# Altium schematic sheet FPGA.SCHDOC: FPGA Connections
size A2; Organization: Altium Limited.; Address1: Level 3, 12a Rodborough Rd; Address2: Frenchs Forest 2086; Address3: NSW; Address4: AUSTRALIA; SheetNumber: 6; SheetTotal: 19; PageSetup: Record=PageOptions|CenterHorizontal=True|CenterVertical=True|PrintScale=0.71|XCorrection=1.00|YCorrection=1.00|PrintKind=0|BorderSize=5000000|LeftOffset=0|BottomOffset=0|Orientation=2|PaperLength=1000|PaperWidth=1000|Scale=100|PaperSource=7|PrintQuality=600|MediaType=1|DitherType=10|PaperKind=A3 (297 x 420mm)|PrintScaleMode=1
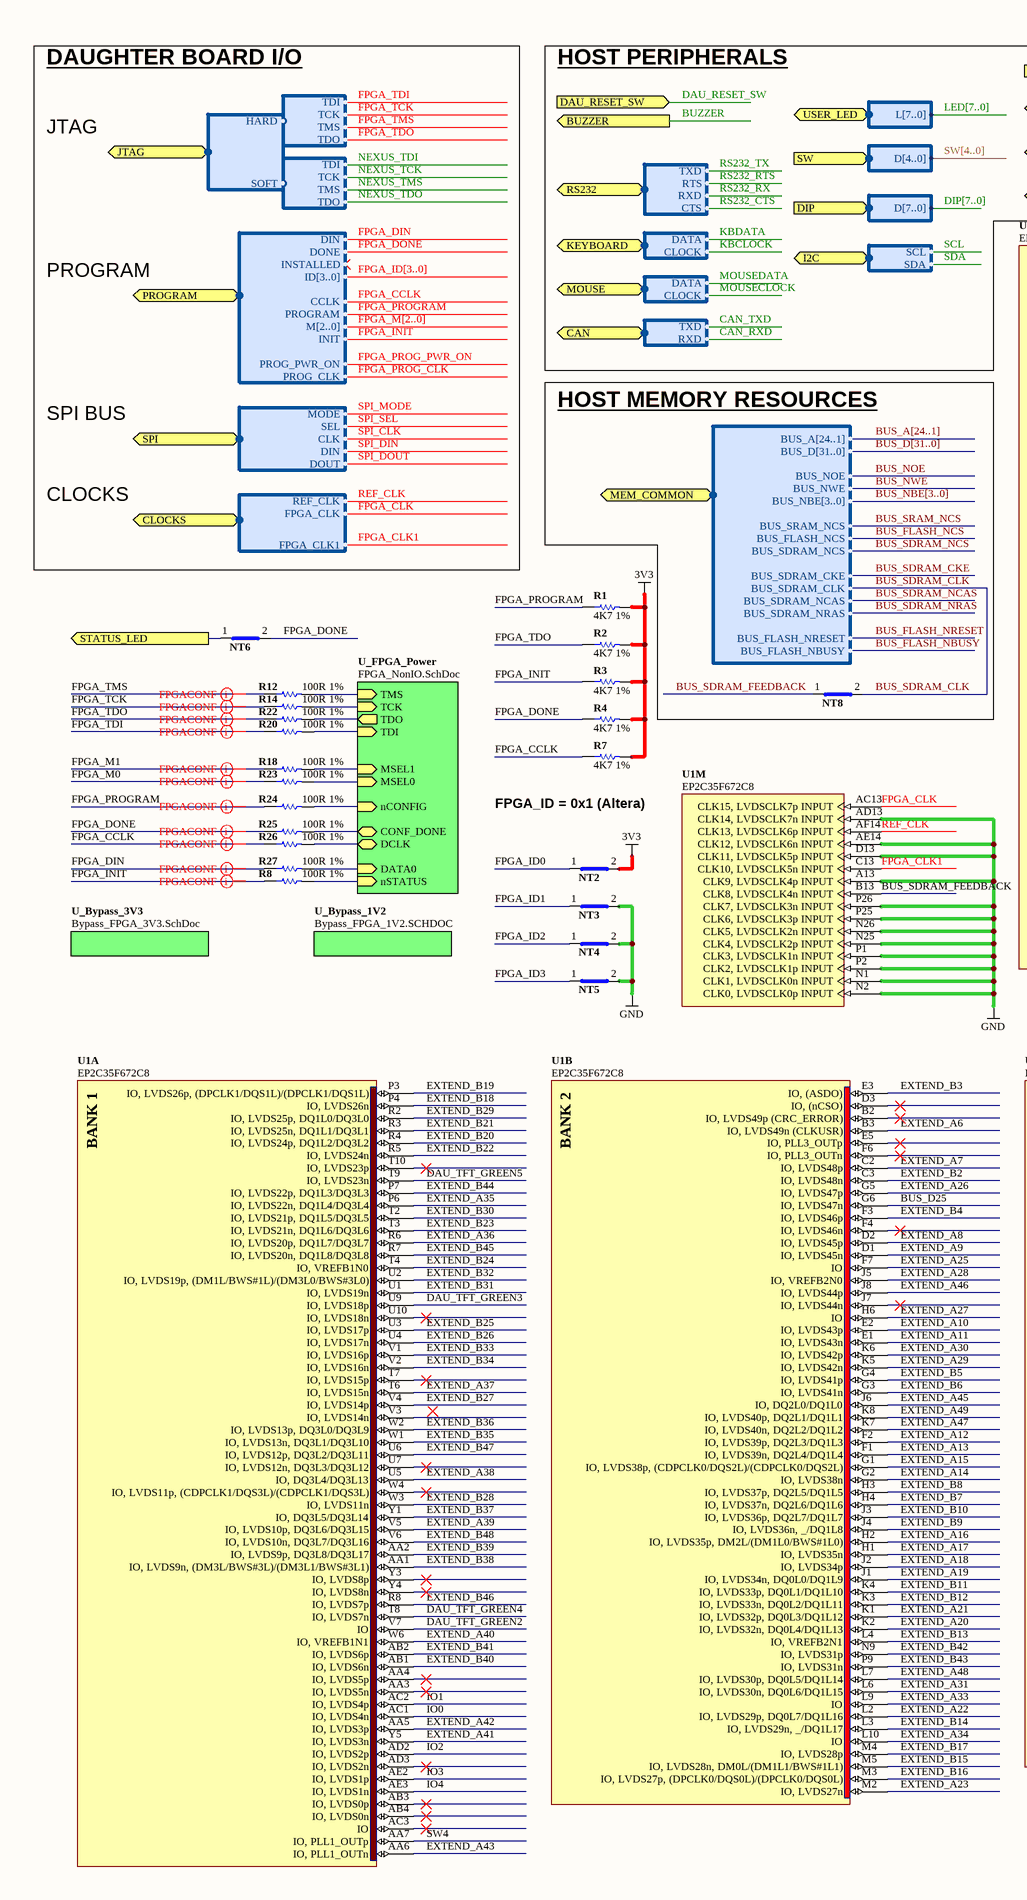
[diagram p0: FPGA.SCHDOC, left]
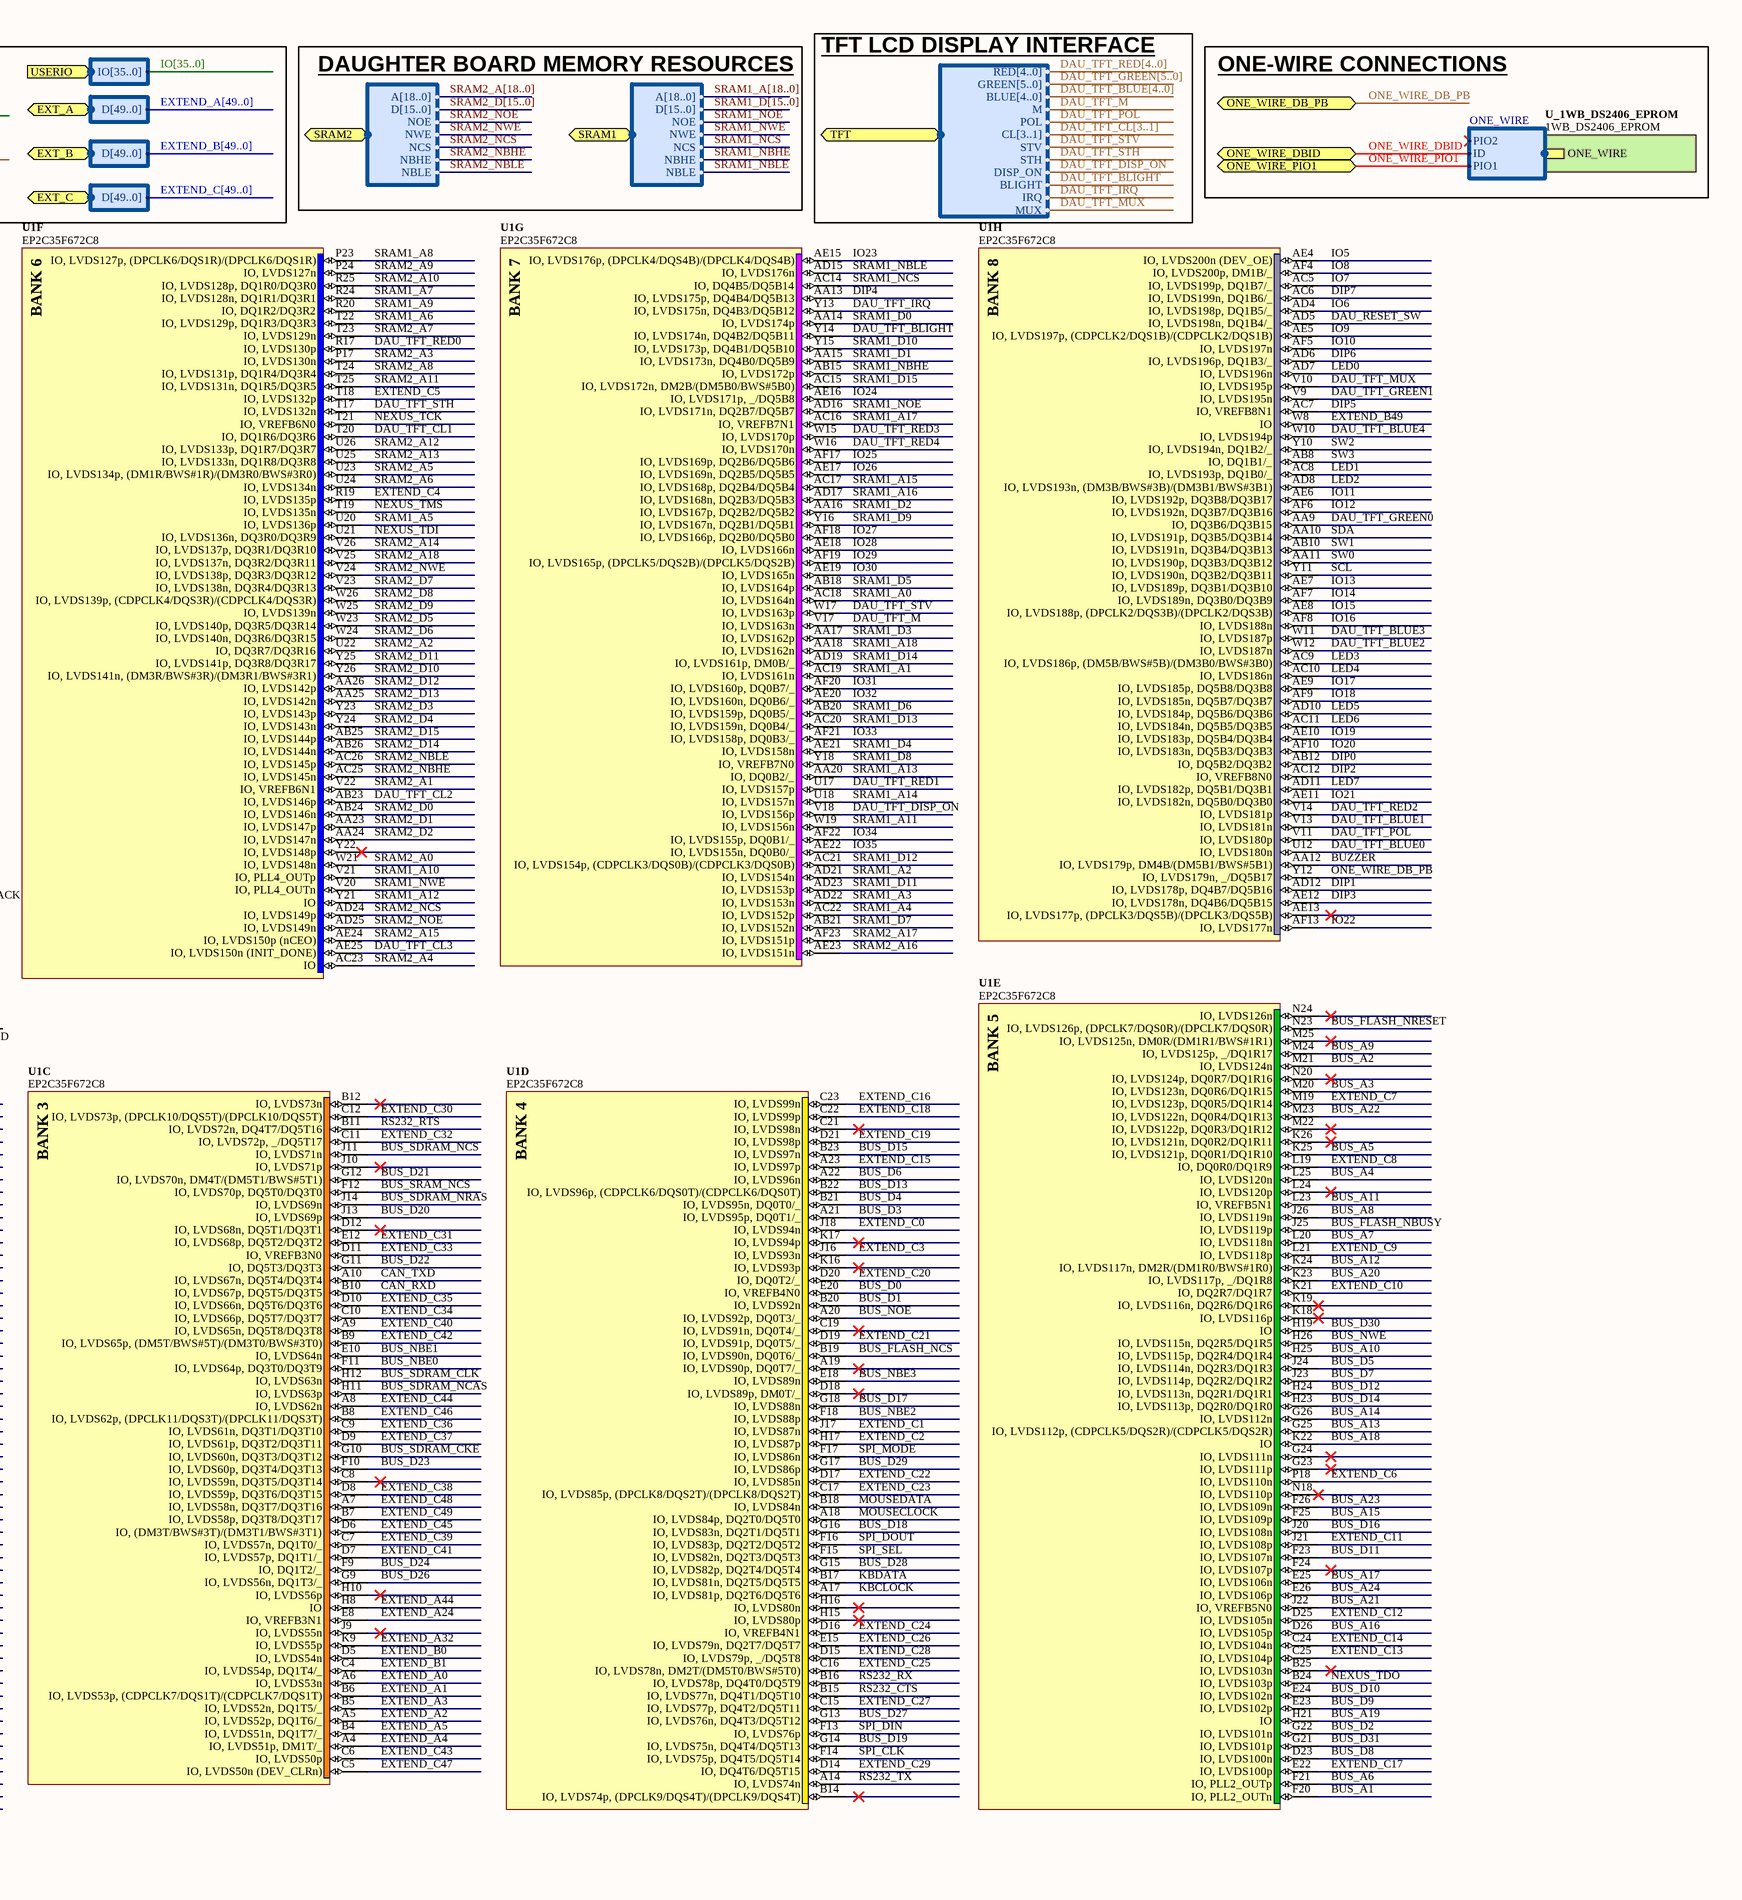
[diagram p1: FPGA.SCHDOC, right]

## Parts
NT2  Net Tie SMT2  [NETTIE-SMT2-8X8]  (value not drawn)  (net tie, no BOM)
NT3  Net Tie SMT2  [NETTIE-SMT2-8X8]  (value not drawn)  (net tie, no BOM)
NT4  Net Tie SMT2  [NETTIE-SMT2-8X8]  (value not drawn)  (net tie, no BOM)
NT5  Net Tie SMT2  [NETTIE-SMT2-8X8]  (value not drawn)  (net tie, no BOM)
NT6  Net Tie SMT2  [NETTIE-SMT2-8X8]  (value not drawn)  (net tie, no BOM)
NT8  Net Tie SMT2  [NETTIE-SMT2-8X8]  (value not drawn)  (net tie, no BOM)
R1  4K7 1%  [RESC1005-STAR]
R2  4K7 1%  [RESC1005-STAR]
R3  4K7 1%  [RESC1005-STAR]
R4  4K7 1%  [RESC1005-STAR]
R7  4K7 1%  [RESC1005-STAR]
R8  100R 1%  [RESC1005-STAR]
R12  100R 1%  [RESC1005-STAR]
R14  100R 1%  [RESC1005-STAR]
R18  100R 1%  [RESC1005-STAR]
R20  100R 1%  [RESC1005-STAR]
R22  100R 1%  [RESC1005-STAR]
R23  100R 1%  [RESC1005-STAR]
R24  100R 1%  [RESC1005-STAR]
R25  100R 1%  [RESC1005-STAR]
R26  100R 1%  [RESC1005-STAR]
R27  100R 1%  [RESC1005-STAR]
U1  EP2C35F672C8  [BGA100P26X26-672]  (parts A,B,C,D,E,F,G,H,M of 14)

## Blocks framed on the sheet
HOST MEMORY RESOURCES: NT8

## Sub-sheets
U_1WB_DS2406_EPROM = 1WB_DS2406_EPROM: ONE_WIRE (harness ONE_WIRE)
U_Bypass_1V2 = Bypass_FPGA_1V2.SCHDOC: no entries
U_Bypass_3V3 = Bypass_FPGA_3V3.SchDoc: no entries
U_FPGA_Power = FPGA_NonIO.SchDoc: TMS (in), CONF_DONE (bidir), MSEL1 (in), DCLK (bidir), MSEL0 (in), DATA0 (in), TCK (in), nSTATUS (in), TDI (in), nCONFIG (in), TDO (out)

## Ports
BUZZER (out), CAN (harness CAN_INT), CLOCKS (harness DAU_CLK), DAU_RESET_SW (in), DIP (harness SW8), EXT_A (harness PBIO), EXT_B (harness PBIO), EXT_C (harness PBIO), I2C (harness I2C), JTAG (harness HARDSOFT_JTAG), KEYBOARD (harness PS2), MEM_COMMON (harness HOSTMEMORY), MOUSE (harness PS2), ONE_WIRE_DB_PB (bidir), ONE_WIRE_DBID (bidir), ONE_WIRE_PIO1 (bidir), PROGRAM (harness DAU_CTRL), RS232 (harness RS232_INT), SPI (harness DAU_SPI), SRAM1 (harness SRAM-256Kx16), SRAM2 (harness SRAM-256Kx16), STATUS_LED (out), SW (harness SW5), TFT (harness DAU_TFT), USER_LED (harness LED8), USERIO (harness IO36)

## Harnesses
ONE_WIRE: ID, PIO1, PIO2
DAU_CLK: REF_CLK, FPGA_CLK, FPGA_CLK1
DAU_SPI: MODE, SEL, CLK, DIN, DOUT
DAU_CTRL: DIN, DONE, INSTALLED, ID[3..0], CCLK, PROGRAM, M[2..0], INIT, PROG_PWR_ON, PROG_CLK
JTAG: TMS, TDO, TDI, TCK
HARDSOFT_JTAG: HARD, SOFT
DAU_TFT: RED[4..0], GREEN[5..0], BLUE[4..0], M, POL, CL[3..1], STV, STH, DISP_ON, BLIGHT, IRQ, MUX
SRAM-256Kx16: A[18..0], D[15..0], NCS, NWE, NOE, NBHE, NBLE
HOSTMEMORY: BUS_A[24..1], BUS_D[31..0], BUS_NOE, BUS_NWE, BUS_NBE[3..0], BUS_SRAM_NCS, BUS_FLASH_NCS, BUS_SDRAM_NCS, BUS_SDRAM_CKE, BUS_SDRAM_CLK, BUS_SDRAM_NCAS, BUS_SDRAM_NRAS, BUS_FLASH_NRESET, BUS_FLASH_NBUSY
LED8: L[7..0]
SW5: D[4..0]
PS2: DATA, CLOCK
RS232_INT: RXD, TXD, RTS, CTS
PBIO: D[49..0]
IO36: IO[35..0]
SW8: D[7..0]
CAN_INT: TXD, RXD
I2C: SCL, SDA

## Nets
3V3: NT2.2(Net2) R1.2 R2.2 R3.2 R4.2 R7.2
GND: NT3.2(Net2) NT4.2(Net2) NT5.2(Net2) U1.A13(CLK9,_LVDSCLK4p_INPUT) U1.AD13(CLK14,_LVDSCLK7n_INPUT) U1.AE14(CLK12,_LVDSCLK6n_INPUT) U1.D13(CLK11,_LVDSCLK5p_INPUT) U1.N1(CLK1,_LVDSCLK0n_INPUT) U1.N2(CLK0,_LVDSCLK0p_INPUT) U1.N25(CLK4,_LVDSCLK2p_INPUT) U1.N26(CLK5,_LVDSCLK2n_INPUT) U1.P1(CLK3,_LVDSCLK1n_INPUT) U1.P2(CLK2,_LVDSCLK1p_INPUT) U1.P25(CLK6,_LVDSCLK3p_INPUT) U1.P26(CLK7,_LVDSCLK3n_INPUT)
BUS_A1: U1.F20(IO,_PLL2_OUTn)
BUS_A2: U1.M21(IO,_LVDS124n)
BUS_A3: U1.M20(IO,_LVDS123n,_DQ0R6/DQ1R15)
BUS_A4: U1.L25(IO,_LVDS120n)
BUS_A5: U1.K25(IO,_LVDS121p,_DQ0R1/DQ1R10)
BUS_A6: U1.F21(IO,_PLL2_OUTp)
BUS_A7: U1.L20(IO,_LVDS118n)
BUS_A8: U1.J26(IO,_LVDS119n)
BUS_A9: U1.M24(IO,_LVDS125p,__/DQ1R17)
BUS_A10: U1.H25(IO,_LVDS115p,_DQ2R4/DQ1R4)
BUS_A11: U1.L23(IO,_VREFB5N1)
BUS_A12: U1.K24(IO,_LVDS117n,_DM2R/(DM1R0/BWS#1R0))
BUS_A13: U1.G25(IO,_LVDS112p,_(CDPCLK5/DQS2R)/(CDPCLK5/DQS2R))
BUS_A14: U1.G26(IO,_LVDS112n)
BUS_A15: U1.F25(IO,_LVDS109p)
BUS_A16: U1.D26(IO,_LVDS105p)
BUS_A17: U1.E25(IO,_LVDS106n)
BUS_A18: U1.K22(IO)
BUS_A19: U1.H21(IO)
BUS_A20: U1.K23(IO,_LVDS117p,__/DQ1R8)
BUS_A21: U1.J22(IO,_VREFB5N0)
BUS_A22: U1.M23(IO,_LVDS122n,_DQ0R4/DQ1R13)
BUS_A23: U1.F26(IO,_LVDS109n)
BUS_A24: U1.E26(IO,_LVDS106p)
BUS_D0: U1.E20(IO,_VREFB4N0)
BUS_D1: U1.B20(IO,_LVDS92n)
BUS_D2: U1.G22(IO,_LVDS101n)
BUS_D3: U1.A21(IO,_LVDS95p,_DQ0T1/_)
BUS_D4: U1.B21(IO,_LVDS95n,_DQ0T0/_)
BUS_D5: U1.J24(IO,_LVDS114n,_DQ2R3/DQ1R3)
BUS_D6: U1.A22(IO,_LVDS96n)
BUS_D7: U1.J23(IO,_LVDS114p,_DQ2R2/DQ1R2)
BUS_D8: U1.D23(IO,_LVDS100n)
BUS_D9: U1.E23(IO,_LVDS102p)
BUS_D10: U1.E24(IO,_LVDS102n)
BUS_D11: U1.F23(IO,_LVDS107n)
BUS_D12: U1.H24(IO,_LVDS113n,_DQ2R1/DQ1R1)
BUS_D13: U1.B22(IO,_LVDS96p,_(CDPCLK6/DQS0T)/(CDPCLK6/DQS0T))
BUS_D14: U1.H23(IO,_LVDS113p,_DQ2R0/DQ1R0)
BUS_D15: U1.B23(IO,_LVDS97n)
BUS_D16: U1.J20(IO,_LVDS108n)
BUS_D17: U1.G18(IO,_LVDS88n)
BUS_D18: U1.G16(IO,_LVDS83n,_DQ2T1/DQ5T1)
BUS_D19: U1.G14(IO,_LVDS75n,_DQ4T4/DQ5T13)
BUS_D20: U1.J13(IO,_LVDS69p)
BUS_D21: U1.G12(IO,_LVDS70n,_DM4T/(DM5T1/BWS#5T1))
BUS_D22: U1.G11(IO,_DQ5T3/DQ3T3)
BUS_D23: U1.F10(IO,_LVDS60p,_DQ3T4/DQ3T13)
BUS_D24: U1.F9(IO,_DQ1T2/_)
BUS_D25: U1.G6(IO,_LVDS47n)
BUS_D26: U1.G9(IO,_LVDS56n,_DQ1T3/_)
BUS_D27: U1.G13(IO,_LVDS76n,_DQ4T3/DQ5T12)
BUS_D28: U1.G15(IO,_LVDS82p,_DQ2T4/DQ5T4)
BUS_D29: U1.G17(IO,_LVDS86p)
BUS_D30: U1.H19(IO)
BUS_D31: U1.G21(IO,_LVDS101p)
BUS_FLASH_NBUSY: U1.J25(IO,_LVDS119p) ; port MEM_COMMON.BUS_FLASH_NBUSY
BUS_FLASH_NCS: U1.B19(IO,_LVDS90n,_DQ0T6/_) ; port MEM_COMMON.BUS_FLASH_NCS
BUS_FLASH_NRESET: U1.N23(IO,_LVDS126p,_(DPCLK7/DQS0R)/(DPCLK7/DQS0R)) ; port MEM_COMMON.BUS_FLASH_NRESET
BUS_NBE0: U1.F11(IO,_LVDS64p,_DQ3T0/DQ3T9)
BUS_NBE1: U1.E10(IO,_LVDS64n)
BUS_NBE2: U1.F18(IO,_LVDS88p)
BUS_NBE3: U1.E18(IO,_LVDS89n)
BUS_NOE: U1.A20(IO,_LVDS92p,_DQ0T3/_) ; port MEM_COMMON.BUS_NOE
BUS_NWE: U1.H26(IO,_LVDS115n,_DQ2R5/DQ1R5) ; port MEM_COMMON.BUS_NWE
BUS_SDRAM_CKE: U1.G10(IO,_LVDS60n,_DQ3T3/DQ3T12) ; port MEM_COMMON.BUS_SDRAM_CKE
BUS_SDRAM_CLK: NT8.2(Net2) U1.H12(IO,_LVDS63n) ; port MEM_COMMON.BUS_SDRAM_CLK
BUS_SDRAM_FEEDBACK: NT8.1(Net1) U1.B13(CLK8,_LVDSCLK4n_INPUT)
BUS_SDRAM_NCAS: U1.H11(IO,_LVDS63p) ; port MEM_COMMON.BUS_SDRAM_NCAS
BUS_SDRAM_NCS: U1.J11(IO,_LVDS71n) ; port MEM_COMMON.BUS_SDRAM_NCS
BUS_SDRAM_NRAS: U1.J14(IO,_LVDS69n) ; port MEM_COMMON.BUS_SDRAM_NRAS
BUS_SRAM_NCS: U1.F12(IO,_LVDS70p,_DQ5T0/DQ3T0) ; port MEM_COMMON.BUS_SRAM_NCS
BUZZER: U1.AA12(IO,_LVDS179p,_DM4B/(DM5B1/BWS#5B1)) ; port BUZZER
CAN_RXD: U1.B10(IO,_LVDS67p,_DQ5T5/DQ3T5) ; port CAN.RXD
CAN_TXD: U1.A10(IO,_LVDS67n,_DQ5T4/DQ3T4) ; port CAN.TXD
DAU_RESET_SW: U1.AD5(IO,_LVDS198n,_DQ1B4/_) ; port DAU_RESET_SW
DAU_TFT_BLIGHT: U1.Y14(IO,_LVDS174n,_DQ4B2/DQ5B11) ; port TFT.BLIGHT
DAU_TFT_BLUE0: U1.U12(IO,_LVDS180n)
DAU_TFT_BLUE1: U1.V13(IO,_LVDS181n)
DAU_TFT_BLUE2: U1.W12(IO,_LVDS187n)
DAU_TFT_BLUE3: U1.W11(IO,_LVDS187p)
DAU_TFT_BLUE4: U1.W10(IO,_LVDS194p)
DAU_TFT_CL1: U1.T20(IO,_DQ1R6/DQ3R6)
DAU_TFT_CL2: U1.AB23(IO,_LVDS146p)
DAU_TFT_CL3: U1.AE25(IO,_LVDS150n_(INIT_DONE))
DAU_TFT_DISP_ON: U1.V18(IO,_LVDS156p) ; port TFT.DISP_ON
DAU_TFT_GREEN0: U1.AA9(IO,_DQ3B6/DQ3B15)
DAU_TFT_GREEN1: U1.V9(IO,_LVDS195n)
DAU_TFT_GREEN2: U1.V7(IO)
DAU_TFT_GREEN3: U1.U9(IO,_LVDS18p)
DAU_TFT_GREEN4: U1.T8(IO,_LVDS7n)
DAU_TFT_GREEN5: U1.T9(IO,_LVDS23n)
DAU_TFT_IRQ: U1.Y13(IO,_LVDS175n,_DQ4B3/DQ5B12) ; port TFT.IRQ
DAU_TFT_M: U1.V17(IO,_LVDS163n) ; port TFT.M
DAU_TFT_MUX: U1.V10(IO,_LVDS195p) ; port TFT.MUX
DAU_TFT_POL: U1.V11(IO,_LVDS180p) ; port TFT.POL
DAU_TFT_RED0: U1.R17(IO,_LVDS130p)
DAU_TFT_RED1: U1.U17(IO,_LVDS157p)
DAU_TFT_RED2: U1.V14(IO,_LVDS181p)
DAU_TFT_RED3: U1.W15(IO,_LVDS170p)
DAU_TFT_RED4: U1.W16(IO,_LVDS170n)
DAU_TFT_STH: U1.T17(IO,_LVDS132n) ; port TFT.STH
DAU_TFT_STV: U1.W17(IO,_LVDS163p) ; port TFT.STV
DIP0: U1.AB12(IO,_DQ5B2/DQ3B2)
DIP1: U1.AD12(IO,_LVDS178p,_DQ4B7/DQ5B16)
DIP2: U1.AC12(IO,_VREFB8N0)
DIP3: U1.AE12(IO,_LVDS178n,_DQ4B6/DQ5B15)
DIP4: U1.AA13(IO,_LVDS175p,_DQ4B4/DQ5B13)
DIP5: U1.AC7(IO,_VREFB8N1)
DIP6: U1.AD6(IO,_LVDS196p,_DQ1B3/_)
DIP7: U1.AC6(IO,_LVDS199n,_DQ1B6/_)
EXTEND_A0: U1.A6(IO,_LVDS53n)
EXTEND_A1: U1.B6(IO,_LVDS53p,_(CDPCLK7/DQS1T)/(CDPCLK7/DQS1T))
EXTEND_A2: U1.A5(IO,_LVDS52p,_DQ1T6/_)
EXTEND_A3: U1.B5(IO,_LVDS52n,_DQ1T5/_)
EXTEND_A4: U1.A4(IO,_LVDS51p,_DM1T/_)
EXTEND_A5: U1.B4(IO,_LVDS51n,_DQ1T7/_)
EXTEND_A6: U1.B3(IO,_LVDS49n_(CLKUSR))
EXTEND_A7: U1.C2(IO,_LVDS48p)
EXTEND_A8: U1.D2(IO,_LVDS45p)
EXTEND_A9: U1.D1(IO,_LVDS45n)
EXTEND_A10: U1.E2(IO,_LVDS43p)
EXTEND_A11: U1.E1(IO,_LVDS43n)
EXTEND_A12: U1.F2(IO,_LVDS39p,_DQ2L3/DQ1L3)
EXTEND_A13: U1.F1(IO,_LVDS39n,_DQ2L4/DQ1L4)
EXTEND_A14: U1.G2(IO,_LVDS38n)
EXTEND_A15: U1.G1(IO,_LVDS38p,_(CDPCLK0/DQS2L)/(CDPCLK0/DQS2L))
EXTEND_A16: U1.H2(IO,_LVDS35p,_DM2L/(DM1L0/BWS#1L0))
EXTEND_A17: U1.H1(IO,_LVDS35n)
EXTEND_A18: U1.J2(IO,_LVDS34p)
EXTEND_A19: U1.J1(IO,_LVDS34n,_DQ0L0/DQ1L9)
EXTEND_A20: U1.K2(IO,_LVDS32n,_DQ0L4/DQ1L13)
EXTEND_A21: U1.K1(IO,_LVDS32p,_DQ0L3/DQ1L12)
EXTEND_A22: U1.L2(IO,_LVDS29p,_DQ0L7/DQ1L16)
EXTEND_A23: U1.M2(IO,_LVDS27n)
EXTEND_A24: U1.E8(IO,_VREFB3N1)
EXTEND_A25: U1.F7(IO)
EXTEND_A26: U1.G5(IO,_LVDS47p)
EXTEND_A27: U1.H6(IO)
EXTEND_A28: U1.J5(IO,_VREFB2N0)
EXTEND_A29: U1.K5(IO,_LVDS42n)
EXTEND_A30: U1.K6(IO,_LVDS42p)
EXTEND_A31: U1.L6(IO,_LVDS30n,_DQ0L6/DQ1L15)
EXTEND_A32: U1.K9(IO,_LVDS55p)
EXTEND_A33: U1.L9(IO)
EXTEND_A34: U1.L10(IO)
EXTEND_A35: U1.P6(IO,_LVDS22n,_DQ1L4/DQ3L4)
EXTEND_A36: U1.R6(IO,_LVDS20p,_DQ1L7/DQ3L7)
EXTEND_A37: U1.T6(IO,_LVDS15n)
EXTEND_A38: U1.U5(IO,_DQ3L4/DQ3L13)
EXTEND_A39: U1.V5(IO,_LVDS10p,_DQ3L6/DQ3L15)
EXTEND_A40: U1.W6(IO,_VREFB1N1)
EXTEND_A41: U1.Y5(IO,_LVDS3n)
EXTEND_A42: U1.AA5(IO,_LVDS3p)
EXTEND_A43: U1.AA6(IO,_PLL1_OUTn)
EXTEND_A44: U1.H8(IO)
EXTEND_A45: U1.J6(IO,_DQ2L0/DQ1L0)
EXTEND_A46: U1.J8(IO,_LVDS44p)
EXTEND_A47: U1.K7(IO,_LVDS40n,_DQ2L2/DQ1L2)
EXTEND_A48: U1.L7(IO,_LVDS30p,_DQ0L5/DQ1L14)
EXTEND_A49: U1.K8(IO,_LVDS40p,_DQ2L1/DQ1L1)
EXTEND_B0: U1.D5(IO,_LVDS54n)
EXTEND_B1: U1.C4(IO,_LVDS54p,_DQ1T4/_)
EXTEND_B2: U1.C3(IO,_LVDS48n)
EXTEND_B3: U1.E3(IO,_(ASDO))
EXTEND_B4: U1.F3(IO,_LVDS46p)
EXTEND_B5: U1.G4(IO,_LVDS41p)
EXTEND_B6: U1.G3(IO,_LVDS41n)
EXTEND_B7: U1.H4(IO,_LVDS37n,_DQ2L6/DQ1L6)
EXTEND_B8: U1.H3(IO,_LVDS37p,_DQ2L5/DQ1L5)
EXTEND_B9: U1.J4(IO,_LVDS36n,__/DQ1L8)
EXTEND_B10: U1.J3(IO,_LVDS36p,_DQ2L7/DQ1L7)
EXTEND_B11: U1.K4(IO,_LVDS33p,_DQ0L1/DQ1L10)
EXTEND_B12: U1.K3(IO,_LVDS33n,_DQ0L2/DQ1L11)
EXTEND_B13: U1.L4(IO,_VREFB2N1)
EXTEND_B14: U1.L3(IO,_LVDS29n,__/DQ1L17)
EXTEND_B15: U1.M5(IO,_LVDS28n,_DM0L/(DM1L1/BWS#1L1))
EXTEND_B16: U1.M3(IO,_LVDS27p,_(DPCLK0/DQS0L)/(DPCLK0/DQS0L))
EXTEND_B17: U1.M4(IO,_LVDS28p)
EXTEND_B18: U1.P4(IO,_LVDS26n)
EXTEND_B19: U1.P3(IO,_LVDS26p,_(DPCLK1/DQS1L)/(DPCLK1/DQS1L))
EXTEND_B20: U1.R4(IO,_LVDS24p,_DQ1L2/DQ3L2)
EXTEND_B21: U1.R3(IO,_LVDS25n,_DQ1L1/DQ3L1)
EXTEND_B22: U1.R5(IO,_LVDS24n)
EXTEND_B23: U1.T3(IO,_LVDS21n,_DQ1L6/DQ3L6)
EXTEND_B24: U1.T4(IO,_VREFB1N0)
EXTEND_B25: U1.U3(IO,_LVDS17p)
EXTEND_B26: U1.U4(IO,_LVDS17n)
EXTEND_B27: U1.V4(IO,_LVDS14p)
EXTEND_B28: U1.W3(IO,_LVDS11n)
EXTEND_B29: U1.R2(IO,_LVDS25p,_DQ1L0/DQ3L0)
EXTEND_B30: U1.T2(IO,_LVDS21p,_DQ1L5/DQ3L5)
EXTEND_B31: U1.U1(IO,_LVDS19n)
EXTEND_B32: U1.U2(IO,_LVDS19p,_(DM1L/BWS#1L)/(DM3L0/BWS#3L0))
EXTEND_B33: U1.V1(IO,_LVDS16p)
EXTEND_B34: U1.V2(IO,_LVDS16n)
EXTEND_B35: U1.W1(IO,_LVDS13n,_DQ3L1/DQ3L10)
EXTEND_B36: U1.W2(IO,_LVDS13p,_DQ3L0/DQ3L9)
EXTEND_B37: U1.Y1(IO,_DQ3L5/DQ3L14)
EXTEND_B38: U1.AA1(IO,_LVDS9n,_(DM3L/BWS#3L)/(DM3L1/BWS#3L1))
EXTEND_B39: U1.AA2(IO,_LVDS9p,_DQ3L8/DQ3L17)
EXTEND_B40: U1.AB1(IO,_LVDS6n)
EXTEND_B41: U1.AB2(IO,_LVDS6p)
EXTEND_B42: U1.N9(IO,_LVDS31p)
EXTEND_B43: U1.P9(IO,_LVDS31n)
EXTEND_B44: U1.P7(IO,_LVDS22p,_DQ1L3/DQ3L3)
EXTEND_B45: U1.R7(IO,_LVDS20n,_DQ1L8/DQ3L8)
EXTEND_B46: U1.R8(IO,_LVDS7p)
EXTEND_B47: U1.U6(IO,_LVDS12p,_DQ3L2/DQ3L11)
EXTEND_B48: U1.V6(IO,_LVDS10n,_DQ3L7/DQ3L16)
EXTEND_B49: U1.W8(IO)
EXTEND_C0: U1.J18(IO,_LVDS94n)
EXTEND_C1: U1.J17(IO,_LVDS87n)
EXTEND_C2: U1.H17(IO,_LVDS87p)
EXTEND_C3: U1.J16(IO,_LVDS93n)
EXTEND_C4: U1.R19(IO,_LVDS135p)
EXTEND_C5: U1.T18(IO,_LVDS132p)
EXTEND_C6: U1.P18(IO,_LVDS110n)
EXTEND_C7: U1.M19(IO,_LVDS123p,_DQ0R5/DQ1R14)
EXTEND_C8: U1.L19(IO,_DQ0R0/DQ1R9)
EXTEND_C9: U1.L21(IO,_LVDS118p)
EXTEND_C10: U1.K21(IO,_DQ2R7/DQ1R7)
EXTEND_C11: U1.J21(IO,_LVDS108p)
EXTEND_C12: U1.D25(IO,_LVDS105n)
EXTEND_C13: U1.C25(IO,_LVDS104p)
EXTEND_C14: U1.C24(IO,_LVDS104n)
EXTEND_C15: U1.A23(IO,_LVDS97p)
EXTEND_C16: U1.C23(IO,_LVDS99n)
EXTEND_C17: U1.E22(IO,_LVDS100p)
EXTEND_C18: U1.C22(IO,_LVDS99p)
EXTEND_C19: U1.D21(IO,_LVDS98p)
EXTEND_C20: U1.D20(IO,_DQ0T2/_)
EXTEND_C21: U1.D19(IO,_LVDS91p,_DQ0T5/_)
EXTEND_C22: U1.D17(IO,_LVDS85n)
EXTEND_C23: U1.C17(IO,_LVDS85p,_(DPCLK8/DQS2T)/(DPCLK8/DQS2T))
EXTEND_C24: U1.D16(IO,_VREFB4N1)
EXTEND_C25: U1.C16(IO,_LVDS78n,_DM2T/(DM5T0/BWS#5T0))
EXTEND_C26: U1.E15(IO,_LVDS79n,_DQ2T7/DQ5T7)
EXTEND_C27: U1.C15(IO,_LVDS77p,_DQ4T2/DQ5T11)
EXTEND_C28: U1.D15(IO,_LVDS79p,__/DQ5T8)
EXTEND_C29: U1.D14(IO,_DQ4T6/DQ5T15)
EXTEND_C30: U1.C12(IO,_LVDS73p,_(DPCLK10/DQS5T)/(DPCLK10/DQS5T))
EXTEND_C31: U1.E12(IO,_LVDS68p,_DQ5T2/DQ3T2)
EXTEND_C32: U1.C11(IO,_LVDS72p,__/DQ5T17)
EXTEND_C33: U1.D11(IO,_VREFB3N0)
EXTEND_C34: U1.C10(IO,_LVDS66p,_DQ5T7/DQ3T7)
EXTEND_C35: U1.D10(IO,_LVDS66n,_DQ5T6/DQ3T6)
EXTEND_C36: U1.C9(IO,_LVDS61n,_DQ3T1/DQ3T10)
EXTEND_C37: U1.D9(IO,_LVDS61p,_DQ3T2/DQ3T11)
EXTEND_C38: U1.D8(IO,_LVDS59p,_DQ3T6/DQ3T15)
EXTEND_C39: U1.C7(IO,_LVDS57n,_DQ1T0/_)
EXTEND_C40: U1.A9(IO,_LVDS65n,_DQ5T8/DQ3T8)
EXTEND_C41: U1.D7(IO,_LVDS57p,_DQ1T1/_)
EXTEND_C42: U1.B9(IO,_LVDS65p,_(DM5T/BWS#5T)/(DM3T0/BWS#3T0))
EXTEND_C43: U1.C6(IO,_LVDS50p)
EXTEND_C44: U1.A8(IO,_LVDS62n)
EXTEND_C45: U1.D6(IO,_(DM3T/BWS#3T)/(DM3T1/BWS#3T1))
EXTEND_C46: U1.B8(IO,_LVDS62p,_(DPCLK11/DQS3T)/(DPCLK11/DQS3T))
EXTEND_C47: U1.C5(IO,_LVDS50n_(DEV_CLRn))
EXTEND_C48: U1.A7(IO,_LVDS58n,_DQ3T7/DQ3T16)
EXTEND_C49: U1.B7(IO,_LVDS58p,_DQ3T8/DQ3T17)
FPGA_CCLK: R7.1 R26.1 ; port PROGRAM.CCLK
FPGA_CLK: U1.AC13(CLK15,_LVDSCLK7p_INPUT) ; port CLOCKS.FPGA_CLK
FPGA_CLK1: U1.C13(CLK10,_LVDSCLK5n_INPUT) ; port CLOCKS.FPGA_CLK1
FPGA_DIN: R27.1 ; port PROGRAM.DIN
FPGA_DONE: NT6.2(Net2) R4.1 R25.1 ; port PROGRAM.DONE
FPGA_ID0: NT2.1(Net1)
FPGA_ID1: NT3.1(Net1)
FPGA_ID2: NT4.1(Net1)
FPGA_ID3: NT5.1(Net1)
FPGA_INIT: R3.1 R8.1 ; port PROGRAM.INIT
FPGA_M0: R23.1
FPGA_M1: R18.1
FPGA_PROGRAM: R1.1 R24.1 ; port PROGRAM.PROGRAM
FPGA_TCK: R14.1 ; harness JTAG.TCK
FPGA_TDI: R20.1 ; harness JTAG.TDI
FPGA_TDO: R2.1 R22.1 ; harness JTAG.TDO
FPGA_TMS: R12.1 ; harness JTAG.TMS
IO0: U1.AC1(IO,_LVDS4n)
IO1: U1.AC2(IO,_LVDS4p)
IO2: U1.AD2(IO,_LVDS2p)
IO3: U1.AE2(IO,_LVDS1p)
IO4: U1.AE3(IO,_LVDS1n)
IO5: U1.AE4(IO,_LVDS200n_(DEV_OE))
IO6: U1.AD4(IO,_LVDS198p,_DQ1B5/_)
IO7: U1.AC5(IO,_LVDS199p,_DQ1B7/_)
IO8: U1.AF4(IO,_LVDS200p,_DM1B/_)
IO9: U1.AE5(IO,_LVDS197p,_(CDPCLK2/DQS1B)/(CDPCLK2/DQS1B))
IO10: U1.AF5(IO,_LVDS197n)
IO11: U1.AE6(IO,_LVDS192p,_DQ3B8/DQ3B17)
IO12: U1.AF6(IO,_LVDS192n,_DQ3B7/DQ3B16)
IO13: U1.AE7(IO,_LVDS189p,_DQ3B1/DQ3B10)
IO14: U1.AF7(IO,_LVDS189n,_DQ3B0/DQ3B9)
IO15: U1.AE8(IO,_LVDS188p,_(DPCLK2/DQS3B)/(DPCLK2/DQS3B))
IO16: U1.AF8(IO,_LVDS188n)
IO17: U1.AE9(IO,_LVDS185p,_DQ5B8/DQ3B8)
IO18: U1.AF9(IO,_LVDS185n,_DQ5B7/DQ3B7)
IO19: U1.AE10(IO,_LVDS183p,_DQ5B4/DQ3B4)
IO20: U1.AF10(IO,_LVDS183n,_DQ5B3/DQ3B3)
IO21: U1.AE11(IO,_LVDS182n,_DQ5B0/DQ3B0)
IO22: U1.AF13(IO,_LVDS177n)
IO23: U1.AE15(IO,_LVDS176p,_(DPCLK4/DQS4B)/(DPCLK4/DQS4B))
IO24: U1.AE16(IO,_LVDS171p,__/DQ5B8)
IO25: U1.AF17(IO,_LVDS169p,_DQ2B6/DQ5B6)
IO26: U1.AE17(IO,_LVDS169n,_DQ2B5/DQ5B5)
IO27: U1.AF18(IO,_LVDS166p,_DQ2B0/DQ5B0)
IO28: U1.AE18(IO,_LVDS166n)
IO29: U1.AF19(IO,_LVDS165p,_(DPCLK5/DQS2B)/(DPCLK5/DQS2B))
IO30: U1.AE19(IO,_LVDS165n)
IO31: U1.AF20(IO,_LVDS160p,_DQ0B7/_)
IO32: U1.AE20(IO,_LVDS160n,_DQ0B6/_)
IO33: U1.AF21(IO,_LVDS158p,_DQ0B3/_)
IO34: U1.AF22(IO,_LVDS155p,_DQ0B1/_)
IO35: U1.AE22(IO,_LVDS155n,_DQ0B0/_)
KBCLOCK: U1.A17(IO,_LVDS81p,_DQ2T6/DQ5T6) ; port KEYBOARD.CLOCK
KBDATA: U1.B17(IO,_LVDS81n,_DQ2T5/DQ5T5) ; port KEYBOARD.DATA
LED0: U1.AD7(IO,_LVDS196n)
LED1: U1.AC8(IO,_LVDS193p,_DQ1B0/_)
LED2: U1.AD8(IO,_LVDS193n,_(DM3B/BWS#3B)/(DM3B1/BWS#3B1))
LED3: U1.AC9(IO,_LVDS186p,_(DM5B/BWS#5B)/(DM3B0/BWS#3B0))
LED4: U1.AC10(IO,_LVDS186n)
LED5: U1.AD10(IO,_LVDS184p,_DQ5B6/DQ3B6)
LED6: U1.AC11(IO,_LVDS184n,_DQ5B5/DQ3B5)
LED7: U1.AD11(IO,_LVDS182p,_DQ5B1/DQ3B1)
MOUSECLOCK: U1.A18(IO,_LVDS84p,_DQ2T0/DQ5T0) ; port MOUSE.CLOCK
MOUSEDATA: U1.B18(IO,_LVDS84n) ; port MOUSE.DATA
NEXUS_TCK: U1.T21(IO,_VREFB6N0) ; harness JTAG.TCK
NEXUS_TDI: U1.U21(IO,_LVDS136n,_DQ3R0/DQ3R9) ; harness JTAG.TDI
NEXUS_TDO: U1.B24(IO,_LVDS103p) ; harness JTAG.TDO
NEXUS_TMS: U1.T19(IO,_LVDS135n) ; harness JTAG.TMS
ONE_WIRE_DB_PB: U1.Y12(IO,_LVDS179n,__/DQ5B17) ; port ONE_WIRE_DB_PB
ONE_WIRE_DBID: port ONE_WIRE_DBID, sheet U_1WB_DS2406_EPROM/ONE_WIRE.ID
ONE_WIRE_PIO1: port ONE_WIRE_PIO1, sheet U_1WB_DS2406_EPROM/ONE_WIRE.PIO1
REF_CLK: U1.AF14(CLK13,_LVDSCLK6p_INPUT) ; port CLOCKS.REF_CLK
RS232_CTS: U1.B15(IO,_LVDS77n,_DQ4T1/DQ5T10) ; port RS232.CTS
RS232_RTS: U1.B11(IO,_LVDS72n,_DQ4T7/DQ5T16) ; port RS232.RTS
RS232_RX: U1.B16(IO,_LVDS78p,_DQ4T0/DQ5T9) ; port RS232.RXD
RS232_TX: U1.A14(IO,_LVDS74n) ; port RS232.TXD
SCL: U1.Y11(IO,_LVDS190n,_DQ3B2/DQ3B11) ; port I2C.SCL
SDA: U1.AA10(IO,_LVDS191p,_DQ3B5/DQ3B14) ; port I2C.SDA
SPI_CLK: U1.F14(IO,_LVDS75p,_DQ4T5/DQ5T14) ; port SPI.CLK
SPI_DIN: U1.F13(IO,_LVDS76p) ; port SPI.DIN
SPI_DOUT: U1.F16(IO,_LVDS83p,_DQ2T2/DQ5T2) ; port SPI.DOUT
SPI_MODE: U1.F17(IO,_LVDS86n) ; port SPI.MODE
SPI_SEL: U1.F15(IO,_LVDS82n,_DQ2T3/DQ5T3) ; port SPI.SEL
SRAM1_A0: U1.AC18(IO,_LVDS164n)
SRAM1_A1: U1.AC19(IO,_LVDS161n)
SRAM1_A2: U1.AD21(IO,_LVDS154n)
SRAM1_A3: U1.AD22(IO,_LVDS153n)
SRAM1_A4: U1.AC22(IO,_LVDS152p)
SRAM1_A5: U1.U20(IO,_LVDS136p)
SRAM1_A6: U1.T22(IO,_LVDS129p,_DQ1R3/DQ3R3)
SRAM1_A7: U1.R24(IO,_LVDS128n,_DQ1R1/DQ3R1)
SRAM1_A8: U1.P23(IO,_LVDS127p,_(DPCLK6/DQS1R)/(DPCLK6/DQS1R))
SRAM1_A9: U1.R20(IO,_DQ1R2/DQ3R2)
SRAM1_A10: U1.V21(IO,_PLL4_OUTp)
SRAM1_A11: U1.W19(IO,_LVDS156n)
SRAM1_A12: U1.Y21(IO)
SRAM1_A13: U1.AA20(IO,_DQ0B2/_)
SRAM1_A14: U1.U18(IO,_LVDS157n)
SRAM1_A15: U1.AC17(IO,_LVDS168p,_DQ2B4/DQ5B4)
SRAM1_A16: U1.AD17(IO,_LVDS168n,_DQ2B3/DQ5B3)
SRAM1_A17: U1.AC16(IO,_VREFB7N1)
SRAM1_A18: U1.AA18(IO,_LVDS162n)
SRAM1_D0: U1.AA14(IO,_LVDS174p)
SRAM1_D1: U1.AA15(IO,_LVDS173n,_DQ4B0/DQ5B9)
SRAM1_D2: U1.AA16(IO,_LVDS167p,_DQ2B2/DQ5B2)
SRAM1_D3: U1.AA17(IO,_LVDS162p)
SRAM1_D4: U1.AE21(IO,_LVDS158n)
SRAM1_D5: U1.AB18(IO,_LVDS164p)
SRAM1_D6: U1.AB20(IO,_LVDS159p,_DQ0B5/_)
SRAM1_D7: U1.AB21(IO,_LVDS152n)
SRAM1_D8: U1.Y18(IO,_VREFB7N0)
SRAM1_D9: U1.Y16(IO,_LVDS167n,_DQ2B1/DQ5B1)
SRAM1_D10: U1.Y15(IO,_LVDS173p,_DQ4B1/DQ5B10)
SRAM1_D11: U1.AD23(IO,_LVDS153p)
SRAM1_D12: U1.AC21(IO,_LVDS154p,_(CDPCLK3/DQS0B)/(CDPCLK3/DQS0B))
SRAM1_D13: U1.AC20(IO,_LVDS159n,_DQ0B4/_)
SRAM1_D14: U1.AD19(IO,_LVDS161p,_DM0B/_)
SRAM1_D15: U1.AC15(IO,_LVDS172n,_DM2B/(DM5B0/BWS#5B0))
SRAM1_NBHE: U1.AB15(IO,_LVDS172p) ; port SRAM1.NBHE
SRAM1_NBLE: U1.AD15(IO,_LVDS176n) ; port SRAM1.NBLE
SRAM1_NCS: U1.AC14(IO,_DQ4B5/DQ5B14) ; port SRAM1.NCS
SRAM1_NOE: U1.AD16(IO,_LVDS171n,_DQ2B7/DQ5B7) ; port SRAM1.NOE
SRAM1_NWE: U1.V20(IO,_PLL4_OUTn) ; port SRAM1.NWE
SRAM2_A0: U1.W21(IO,_LVDS148n)
SRAM2_A1: U1.V22(IO,_VREFB6N1)
SRAM2_A2: U1.U22(IO,_DQ3R7/DQ3R16)
SRAM2_A3: U1.P17(IO,_LVDS130n)
SRAM2_A4: U1.AC23(IO)
SRAM2_A5: U1.U23(IO,_LVDS134p,_(DM1R/BWS#1R)/(DM3R0/BWS#3R0))
SRAM2_A6: U1.U24(IO,_LVDS134n)
SRAM2_A7: U1.T23(IO,_LVDS129n)
SRAM2_A8: U1.T24(IO,_LVDS131p,_DQ1R4/DQ3R4)
SRAM2_A9: U1.P24(IO,_LVDS127n)
SRAM2_A10: U1.R25(IO,_LVDS128p,_DQ1R0/DQ3R0)
SRAM2_A11: U1.T25(IO,_LVDS131n,_DQ1R5/DQ3R5)
SRAM2_A12: U1.U26(IO,_LVDS133p,_DQ1R7/DQ3R7)
SRAM2_A13: U1.U25(IO,_LVDS133n,_DQ1R8/DQ3R8)
SRAM2_A14: U1.V26(IO,_LVDS137p,_DQ3R1/DQ3R10)
SRAM2_A15: U1.AE24(IO,_LVDS150p_(nCEO))
SRAM2_A16: U1.AE23(IO,_LVDS151n)
SRAM2_A17: U1.AF23(IO,_LVDS151p)
SRAM2_A18: U1.V25(IO,_LVDS137n,_DQ3R2/DQ3R11)
SRAM2_D0: U1.AB24(IO,_LVDS146n)
SRAM2_D1: U1.AA23(IO,_LVDS147p)
SRAM2_D2: U1.AA24(IO,_LVDS147n)
SRAM2_D3: U1.Y23(IO,_LVDS143p)
SRAM2_D4: U1.Y24(IO,_LVDS143n)
SRAM2_D5: U1.W23(IO,_LVDS140p,_DQ3R5/DQ3R14)
SRAM2_D6: U1.W24(IO,_LVDS140n,_DQ3R6/DQ3R15)
SRAM2_D7: U1.V23(IO,_LVDS138n,_DQ3R4/DQ3R13)
SRAM2_D8: U1.W26(IO,_LVDS139p,_(CDPCLK4/DQS3R)/(CDPCLK4/DQS3R))
SRAM2_D9: U1.W25(IO,_LVDS139n)
SRAM2_D10: U1.Y26(IO,_LVDS141n,_(DM3R/BWS#3R)/(DM3R1/BWS#3R1))
SRAM2_D11: U1.Y25(IO,_LVDS141p,_DQ3R8/DQ3R17)
SRAM2_D12: U1.AA26(IO,_LVDS142p)
SRAM2_D13: U1.AA25(IO,_LVDS142n)
SRAM2_D14: U1.AB26(IO,_LVDS144n)
SRAM2_D15: U1.AB25(IO,_LVDS144p)
SRAM2_NBHE: U1.AC25(IO,_LVDS145n) ; port SRAM2.NBHE
SRAM2_NBLE: U1.AC26(IO,_LVDS145p) ; port SRAM2.NBLE
SRAM2_NCS: U1.AD24(IO,_LVDS149p) ; port SRAM2.NCS
SRAM2_NOE: U1.AD25(IO,_LVDS149n) ; port SRAM2.NOE
SRAM2_NWE: U1.V24(IO,_LVDS138p,_DQ3R3/DQ3R12) ; port SRAM2.NWE
STATUS_LED: NT6.1(Net1) ; port STATUS_LED
SW0: U1.AA11(IO,_LVDS190p,_DQ3B3/DQ3B12)
SW1: U1.AB10(IO,_LVDS191n,_DQ3B4/DQ3B13)
SW2: U1.Y10(IO,_LVDS194n,_DQ1B2/_)
SW3: U1.AB8(IO,_DQ1B1/_)
SW4: U1.AA7(IO,_PLL1_OUTp)
NetR8_2: R8.2 ; sheet U_FPGA_Power/nSTATUS
NetR12_2: R12.2 ; sheet U_FPGA_Power/TMS
NetR14_2: R14.2 ; sheet U_FPGA_Power/TCK
NetR18_2: R18.2 ; sheet U_FPGA_Power/MSEL1
NetR20_2: R20.2 ; sheet U_FPGA_Power/TDI
NetR22_2: R22.2 ; sheet U_FPGA_Power/TDO
NetR23_2: R23.2 ; sheet U_FPGA_Power/MSEL0
NetR24_2: R24.2 ; sheet U_FPGA_Power/nCONFIG
NetR25_2: R25.2 ; sheet U_FPGA_Power/CONF_DONE
NetR26_2: R26.2 ; sheet U_FPGA_Power/DCLK
NetR27_2: R27.2 ; sheet U_FPGA_Power/DATA0

Not connected (* = marked no-connect by the designer): U1 A19(IO,_LVDS90p,_DQ0T7/_)* AA3(IO,_LVDS5n)* AA4(IO,_LVDS5p)* AB3(IO,_LVDS0p)* AB4(IO,_LVDS0n)* AC3(IO)* AD3(IO,_LVDS2n)* AE13(IO,_LVDS177p,_(DPCLK3/DQS5B)/(DPCLK3/DQS5B))* B2(IO,_LVDS49p_(CRC_ERROR))* B12(IO,_LVDS73n)* B14(IO,_LVDS74p,_(DPCLK9/DQS4T)/(DPCLK9/DQS4T))* B25(IO,_LVDS103n)* C8(IO,_LVDS59n,_DQ3T5/DQ3T14)* C19(IO,_LVDS91n,_DQ0T4/_)* C21(IO,_LVDS98n)* D3(IO,_(nCSO))* D12(IO,_LVDS68n,_DQ5T1/DQ3T1)* D18(IO,_LVDS89p,_DM0T/_)* E5(IO,_PLL3_OUTp)* F4(IO,_LVDS46n)* F6(IO,_PLL3_OUTn)* F24(IO,_LVDS107p)* G23(IO,_LVDS111p)* G24(IO,_LVDS111n)* H10(IO,_LVDS56p)* H15(IO,_LVDS80p)* H16(IO,_LVDS80n)* J7(IO,_LVDS44n)* J9(IO,_LVDS55n)* J10(IO,_LVDS71p)* K16(IO,_LVDS93p)* K17(IO,_LVDS94p)* K18(IO,_LVDS116p)* K19(IO,_LVDS116n,_DQ2R6/DQ1R6)* K26(IO,_LVDS121n,_DQ0R2/DQ1R11)* L24(IO,_LVDS120p)* M22(IO,_LVDS122p,_DQ0R3/DQ1R12)* M25(IO,_LVDS125n,_DM0R/(DM1R1/BWS#1R1))* N18(IO,_LVDS110p)* N20(IO,_LVDS124p,_DQ0R7/DQ1R16)* N24(IO,_LVDS126n)* T7(IO,_LVDS15p)* T10(IO,_LVDS23p)* U7(IO,_LVDS12n,_DQ3L3/DQ3L12)* U10(IO,_LVDS18n)* V3(IO,_LVDS14n) W4(IO,_LVDS11p,_(CDPCLK1/DQS3L)/(CDPCLK1/DQS3L))* Y3(IO,_LVDS8p)* Y4(IO,_LVDS8n)* Y22(IO,_LVDS148p)*

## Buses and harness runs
bus BUS_A[24..1]
bus BUS_D[31..0]
bus BUS_NBE[3..0]
bus DAU_TFT_BLUE[4..0]
bus DAU_TFT_CL[3..1]
bus DAU_TFT_GREEN[5..0]
bus DAU_TFT_RED[4..0]
bus DIP[7..0]
bus EXTEND_A[49..0]
bus EXTEND_B[49..0]
bus EXTEND_C[49..0]
bus FPGA_ID[3..0]
bus FPGA_M[2..0]
bus IO[35..0]
bus LED[7..0]
bus SRAM1_A[18..0]
bus SRAM1_D[15..0]
bus SRAM2_A[18..0]
bus SRAM2_D[15..0]
bus SW[4..0]

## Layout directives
net class FPGACONF: FPGA_CCLK, FPGA_DIN, FPGA_DONE, FPGA_INIT, FPGA_M0, FPGA_M1, FPGA_PROGRAM, FPGA_TCK, FPGA_TDI, FPGA_TDO, FPGA_TMS

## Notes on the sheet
- DAUGHTER BOARD I/O
- HOST PERIPHERALS
- DAUGHTER BOARD MEMORY RESOURCES
- TFT LCD DISPLAY INTERFACE
- ONE-WIRE CONNECTIONS
- JTAG
- PROGRAM
- SPI BUS
- CLOCKS
- FPGA_ID = 0x1 (Altera)

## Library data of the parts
NT2-NT6 NT8 = D-002-0002: Net-Tie, Surface Mount, 2 x 0.4mm x 0.2mm SMT Pads - For 0.2mm Track
R1-R4 R7 = D-100-0088: Resistor, 4K7 1% 0402 (1005); Power Rating: 63 mW; Resistance: 4.7 K
R8 R12 R14 R18 R20 R22-R27 = D-100-0131: Resistor, 100R 1% 0402 (1005); Power Rating: 63 mW
U1 = D-241-0004: FPGA, Altera Cyclone2-35 F672; Supply Voltage: mV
